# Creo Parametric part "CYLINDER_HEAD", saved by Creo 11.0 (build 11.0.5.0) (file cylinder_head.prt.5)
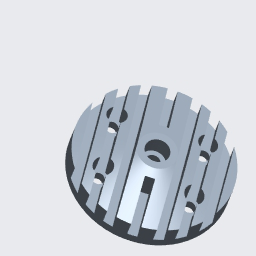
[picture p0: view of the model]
Materials in the file: 10038_S235JR

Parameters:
  MATERIAL = "10038_S235JR"
  PTC_MATERIAL_NAME = "10038_S235JR"
  PTC_MASTER_MATERIAL = "10038_S235JR"
  SELECT_EN_NAME = "S235JR"
  SELECT_DIN_NAME = "RSt37-2"
  SELECT_MATERIAL_NUMBER = "1.0038"
  SELECT_ASTM_NAME = "A 283 M Grade 2"
  MATERIAL_GROUP = "ME_ST_Baustahl"
  STANDARD_EN_DELIVERYSPEC = "DIN EN 10025-2"
  STANDARD_DIN_DELIVERYSPEC = "DIN EN 10025-2"

Other parameters: GEWICHT

Created from: STARTTEIL.PRT

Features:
  1. datum plane "RIGHT"
  2. datum plane "TOP"
  3. datum plane "FRONT"
  4. coordinate system
  5. datum axis
  6. datum axis
  7. datum axis
  8. revolve "Revolve 1"
  9. pattern "Pattern 1"
  10. extruded cut "Extrude 1"
  11. extruded cut "Extrude 1 [2]"
  12. extruded cut "Extrude 1 [3]"
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
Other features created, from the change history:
  extrusion "Extrude 1"
  mirror "Mirror 1"
  pattern "Pattern 1 (2)"
  extruded cut "Extrude 1 (2) [1]"
  extruded cut "Extrude 1 (2) [2]"
  extruded cut "Extrude 1 (2) [3]"
  mirror "Mirror 2"
  pattern "Pattern 1 (3)"
  extruded cut "Extrude 1 (3) [1]"
  extruded cut "Extrude 1 (3) [2]"
  extruded cut "Extrude 1 (3) [3]"
  mirror "Mirror 3"
  pattern "Pattern 1 (4)"
  extruded cut "Extrude 1 (4) [1]"
  extruded cut "Extrude 1 (4) [2]"
  extruded cut "Extrude 1 (4) [3]"
  extruded cut "Extrude 2"
  extruded cut "Extrude 3"
  mirror "Mirror 4"
  extruded cut "Extrude 3 (2)"
  mirror "Mirror 5"
  extruded cut "Extrude 3 (3)"
  mirror "Mirror 6"
  extruded cut "Extrude 3 (4)"
  extruded cut "Extrude 4"
  extruded cut "Extrude 5"
  mirror "Mirror 7"
  extruded cut "Extrude 5 (2)"
  mirror "Mirror 8"
  extruded cut "Extrude 5 (3)"
  mirror "Mirror 9"
  extruded cut "Extrude 5 (4)"
  extruded cut "Extrude 1 [4]" (2 times)
  extruded cut "Extrude 1 (2) [4]"
  extruded cut "Extrude 1 (3) [4]"
  extruded cut "Extrude 1 (4) [4]"
  extruded cut "Extrude 9"
  extruded cut "Extrude 6 [4]"
  extruded cut "Extrude 7 [4]"
  extruded cut "Extrude 8 [4]"
  datum plane "DTM1"
  extrusion "Extrude 9"
  mirror "Mirror 10"
  extruded cut "Extrude 9 (2)"

Other named items: A_Y, A_X, A_Z, CS0

Layers: BEZUGSACHSEN, BEZUGSEBENEN

Surfaces: 29 plane, 12 cylinder, 2 cone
